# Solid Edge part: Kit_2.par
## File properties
Sűrűség: 0,000 kg/m^3
Pontosság: 0,990
Author: bmolnar
Last saved by: bmolnar
Revision: 76
Username: bmolnar
Dokumentum tartalom típus: 0
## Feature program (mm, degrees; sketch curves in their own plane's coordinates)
base feature "unnamed BaseFeature 1"
sketch for "unnamed Hole 1" plane through (-28.25, -28.25, 94) normal (0, 0, 1) x-axis (0, 1, 0)
  hole centre (0, 0) bore radius 3.3235
hole "unnamed Hole 1" through
sketch for "unnamed Hole 2" plane through (-28.25, -28.25, 94) normal (0, 0, 1) x-axis (0, 1, 0)
  hole centre (56.5, 0) bore radius 3.3235
hole "unnamed Hole 2" through
sketch for "unnamed Hole 3" plane through (-28.25, -28.25, 94) normal (0, 0, 1) x-axis (0, 1, 0)
  hole centre (0, -56.5) bore radius 3.3235
hole "unnamed Hole 3" through
sketch for "unnamed Hole 4" plane through (-28.25, -28.25, 94) normal (0, 0, 1) x-axis (0, 1, 0)
  hole centre (56.5, -56.5) bore radius 3.3235
hole "unnamed Hole 4" through
pattern "unnamed Pattern 1" of "unnamed Hole 1", "unnamed Hole 2", "unnamed Hole 3", "unnamed Hole 4"
sketch for "Furat_5" plane through (-38.44, 0, 92.125) normal (-0.999962, 0, 0.008727) x-axis (0, 1, 0)
  hole centre (0, 0.6247) bore radius 4.283
hole "Furat_5" nominal diameter 9.728 finite  ThreadDepth = 10 mm
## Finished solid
Body 1: solid body, 308 faces, 758 edges, 465 vertices.
  Faces by surface: plane 141, cylinder 75, swept 61, cone 20, torus 10, spline 1
  Edges by curve: line 431, circle 154, spline 126, ellipse 30, curve on surface 17
Bounding box of the edges (mm; curved faces can reach further): 77.000 x 77.000 x 13.750, from (-38.5, -38.5, 85.25) to (38.5, 38.5, 99).
Cylindrical faces by radius (mm): R0.2 x48, R0.2008 x2, R0.2009 x2, R0.402 x1, R0.4899 x1, R3.3235 x4, R4.283 x1, R4.9 x4, R5.15 x4, R5.25 x4, R8.27 x1, R8.85 x1, R9 x1, R10.25 x1
Conical faces (half-angle, radius in mm at the cone's reference point): 0.5 deg R12 x4, 0.5 deg R13.5 x2, 7 deg R9.5925 x1, 14 deg R8.135 x1, 14 deg R8.4811 x1, 17 deg R8.135 x1, 23 deg R8.829 x1, 42.5 deg R8.1233 x1, 45 deg R3.6735 x4, 45 deg R9 x1, 84 deg R8.4608 x1, 85 deg R9.9463 x1, 87 deg R8.1765 x1
Toroidal faces (ring radius, tube radius in mm): R4.7 r0.2 x8, R8.8057 r0.2025 x1, R9.2522 r0.2925 x1
Planar faces by outward normal: +x 12, +y 13, +z 19, -x 14, -y 14, -z 1, oblique 68
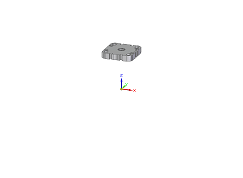
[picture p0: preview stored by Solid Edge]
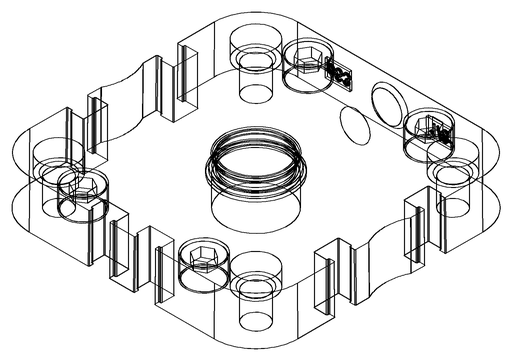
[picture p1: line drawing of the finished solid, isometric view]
